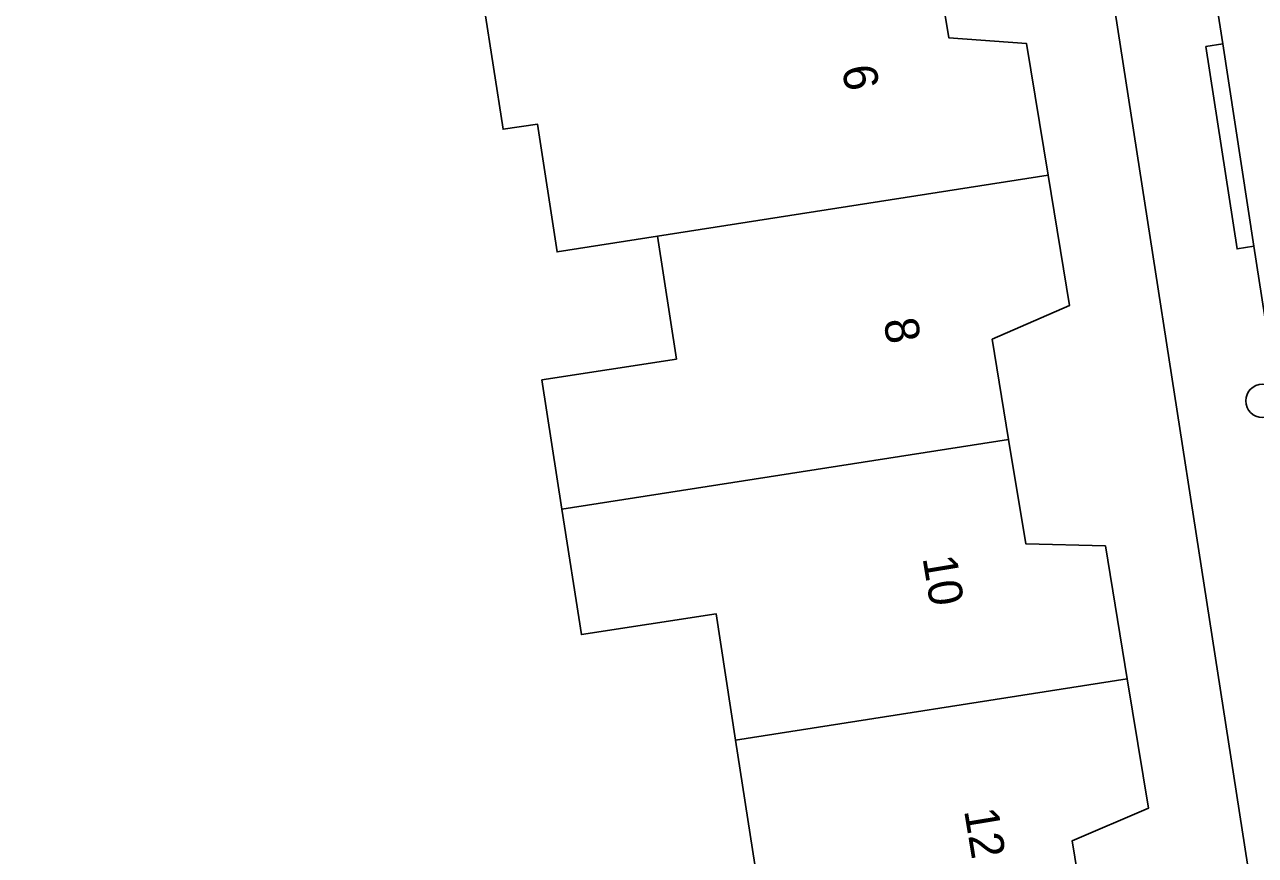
# Model space of a CAD drawing. Extents: x 160077 to 160948, y 386481 to 387498.
# Drawn here: x 160412.23 to 160448.36, y 387143.58 to 387167.98 of the extents above; entities that cross this region are included whole.
import ezdxf

# ---------------------------------------------------------------- set-up
doc = ezdxf.new("R2010")
doc.units = 0
for name, color, linetype in [('IMGEO_Boom', 7, 'Continuous'), ('IMGEO_Erf', 7, 'Continuous'), ('IMGEO_Pand', 7, 'Continuous'), ('IMGEO_Pand_nummerreeks', 7, 'Continuous'), ('IMGEO_Rijbaan_lokaal_open', 7, 'Continuous'), ('IMGEO_Voetpad_open', 7, 'Continuous')]:
    doc.layers.add(name, color=color, linetype=linetype)

msp = doc.modelspace()

# ---------------------------------------------------------------- linework, layer by layer
at = {"layer": 'IMGEO_Boom'}
msp.add_circle((160448.567, 387156.931), 0.489, dxfattribs=at)
at = {"layer": 'IMGEO_Erf'}
for points in [[(160389.598, 387150.682), (160389.931, 387148.86), (160390.592, 387146.738), (160392.013, 387143.711), (160406.951, 387119.747), (160406.038, 387125.066), (160409.218, 387125.612), (160410.167, 387120.084), (160407.072, 387119.553), (160412.74, 387110.46), (160432.671, 387113.564), (160452.281, 387116.619), (160452.082, 387117.899), (160451.862, 387119.314), (160440.112, 387194.954)], [(160438.866, 387170.603), (160439.361, 387167.592), (160441.637, 387167.426), (160442.273, 387163.558), (160442.903, 387159.731), (160440.634, 387158.74), (160441.118, 387155.801), (160441.623, 387152.729), (160443.959, 387152.67), (160444.601, 387148.767), (160445.225, 387144.974), (160442.979, 387144.007), (160443.472, 387141.013)], [(160433.668, 387143.313), (160433.102, 387146.97), (160432.528, 387150.681), (160428.573, 387150.069), (160428.003, 387153.75), (160427.416, 387157.546), (160431.363, 387158.156), (160430.804, 387161.765), (160427.862, 387161.305), (160427.281, 387165.06), (160426.277, 387164.905), (160425.713, 387168.547)]]:
    msp.add_lwpolyline(points, dxfattribs=at)
at = {"layer": 'IMGEO_Pand'}
for points in [[(160441.637, 387167.426), (160439.361, 387167.592), (160438.866, 387170.603), (160425.713, 387168.547), (160426.277, 387164.905), (160427.281, 387165.06), (160427.862, 387161.305), (160430.804, 387161.765), (160442.273, 387163.558)], [(160430.804, 387161.765), (160431.363, 387158.156), (160427.416, 387157.546), (160428.003, 387153.75), (160441.118, 387155.801), (160440.634, 387158.74), (160442.903, 387159.731), (160442.273, 387163.558)], [(160444.601, 387148.767), (160443.959, 387152.67), (160441.623, 387152.729), (160441.118, 387155.801), (160428.003, 387153.75), (160428.573, 387150.069), (160432.528, 387150.681), (160433.102, 387146.97)], [(160433.102, 387146.97), (160433.668, 387143.313), (160429.721, 387142.701), (160430.301, 387138.954), (160443.472, 387141.013), (160442.979, 387144.007), (160445.225, 387144.974), (160444.601, 387148.767)]]:
    msp.add_lwpolyline(points, close=True, dxfattribs=at)
at = {"layer": 'IMGEO_Rijbaan_lokaal_open'}
msp.add_lwpolyline([(160456.269, 387142.466), (160452.642, 387166.52), (160451.698, 387172.524), (160451.124, 387176.171), (160448.647, 387191.915), (160447.856, 387196.313), (160447.484, 387198.268), (160447.442, 387198.531), (160447.437, 387198.56), (160442.512, 387197.622), (160444.978, 387182.595), (160446.013, 387176.282), (160447.401, 387167.413), (160448.319, 387161.471), (160449.654, 387152.837), (160450.551, 387147.034), (160451.402, 387141.525)], dxfattribs=at)
at = {"layer": 'IMGEO_Voetpad_open'}
for points in [[(160451.402, 387141.525), (160450.551, 387147.034), (160450.057, 387146.957), (160449.16, 387152.761), (160449.654, 387152.837), (160448.319, 387161.471), (160447.825, 387161.394), (160446.907, 387167.336), (160447.401, 387167.413), (160446.013, 387176.282), (160445.519, 387176.206), (160444.484, 387182.514), (160444.978, 387182.595), (160442.512, 387197.622)], [(160439.602, 387197.252), (160440.112, 387194.954), (160451.862, 387119.314), (160453.744, 387119.63), (160453.264, 387123.077), (160454.373, 387123.247), (160453.032, 387132.259), (160451.773, 387132.109), (160450.991, 387137.444), (160452.121, 387137.644), (160451.783, 387139.996)]]:
    msp.add_lwpolyline(points, dxfattribs=at)
msp.add_lwpolyline([(160447.401, 387167.413), (160446.907, 387167.336), (160447.825, 387161.394), (160448.319, 387161.471)], close=True, dxfattribs=at)

# ---------------------------------------------------------------- texts
at = {"layer": 'IMGEO_Pand_nummerreeks'}
for s, rotation, p in [('6', 279.339, (160436.221, 387166.719)), ('8', 279.337, (160437.442, 387159.291)), ('10', 279.337, (160438.587, 387152.322)), ('12', 279.337, (160439.807, 387144.903))]:
    msp.add_text(s, height=1, rotation=rotation, dxfattribs=at).set_placement(p)

doc.saveas('drawing.dxf')
